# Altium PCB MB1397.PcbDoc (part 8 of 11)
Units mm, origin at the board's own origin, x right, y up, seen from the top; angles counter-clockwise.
Board outline 118.24 x 172.86 mm, 6 copper layers (Top Layer, L2_GND, L3_VCC, L4_SIG, L5_GND, Bottom Layer), stack 1.631 mm thick; 819 components, 632 nets, 2875 pads, 1523 vias.
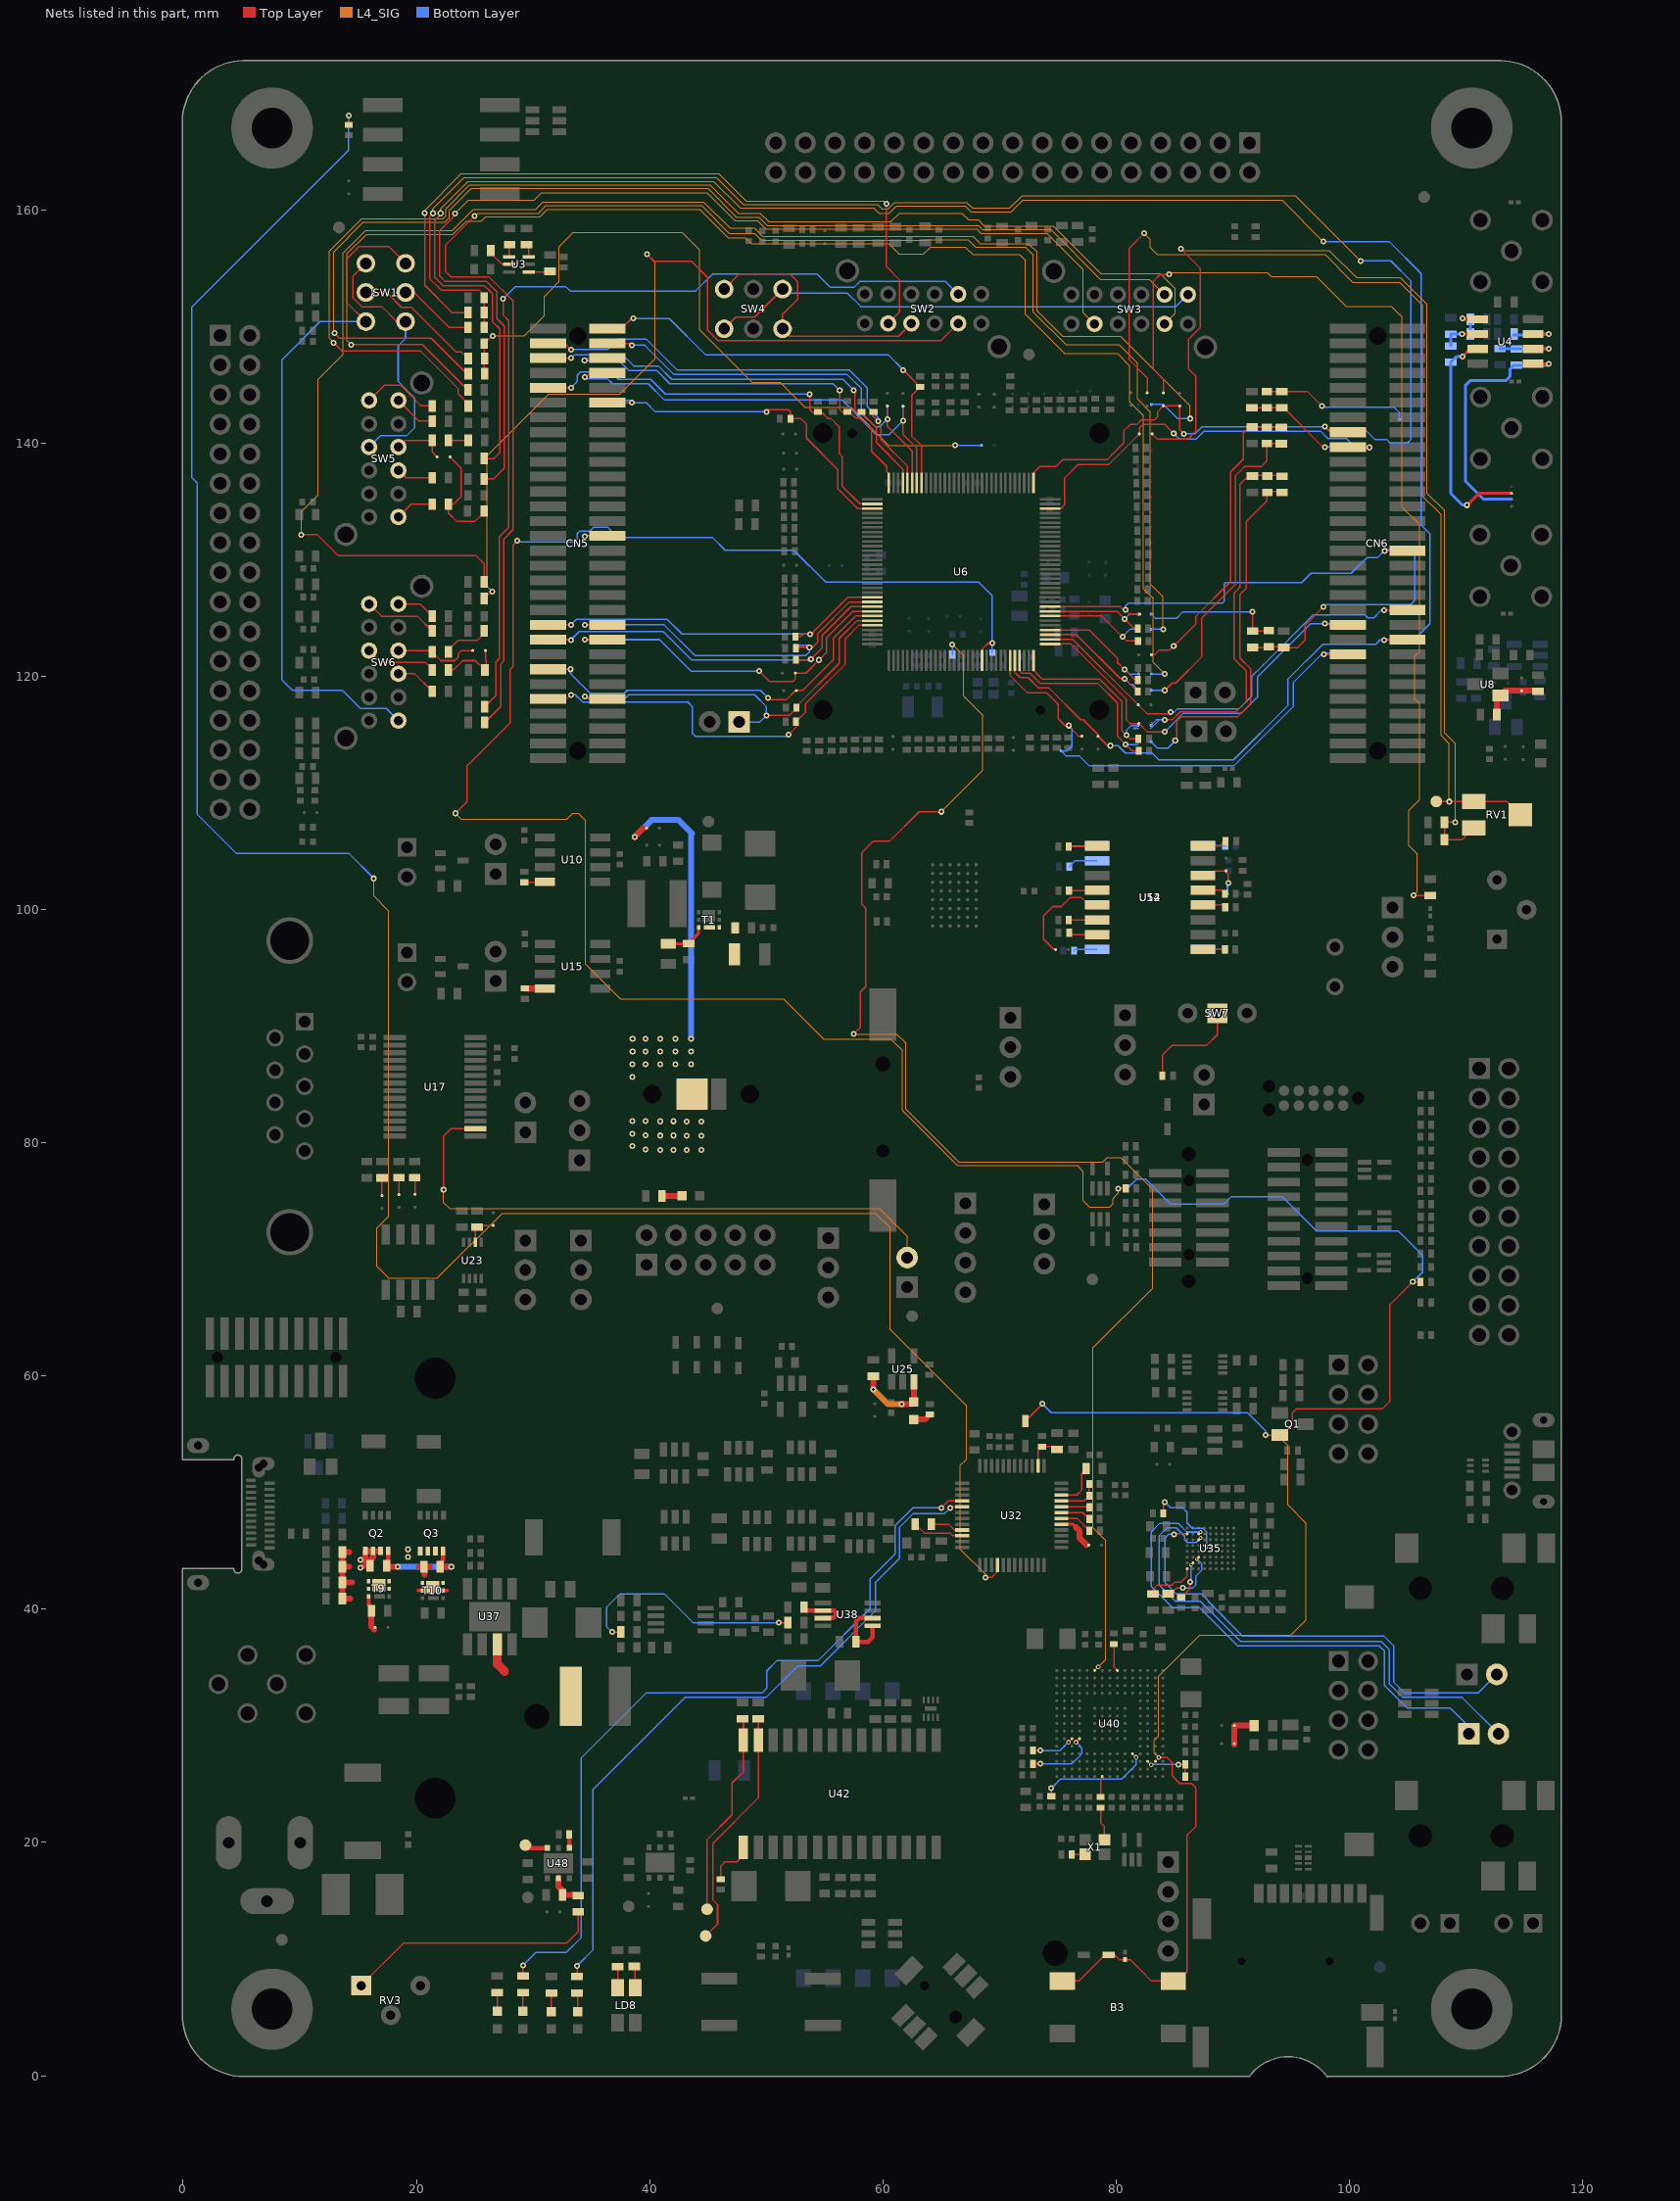
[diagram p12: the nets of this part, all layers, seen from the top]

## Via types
v1: diameter 0.508, hole 0.254, Top Layer to Bottom Layer, tented both sides, 1330 vias
v2: diameter 0.406, hole 0.203, Top Layer to Bottom Layer, tented both sides, 115 vias
v3: diameter 0.508, hole 0.254, Top Layer to Bottom Layer, 33 vias
v4: diameter 0.305, hole 0.152, Top Layer to Bottom Layer, tented both sides, 26 vias
v5: diameter 0.61, hole 0.305, Top Layer to Bottom Layer, tented both sides, 14 vias
v6: diameter 0.61, hole 0.33, Top Layer to Bottom Layer, tented both sides, 2 vias
v7: diameter 0.381, hole 0.203, Top Layer to Bottom Layer, tented both sides, 2 vias
v8: diameter 0.508, hole 0.203, Top Layer to Bottom Layer, tented both sides, 1 vias

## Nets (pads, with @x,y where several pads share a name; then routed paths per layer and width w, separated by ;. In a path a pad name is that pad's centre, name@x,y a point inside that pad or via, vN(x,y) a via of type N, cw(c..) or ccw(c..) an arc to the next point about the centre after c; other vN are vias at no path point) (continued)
NetJP16_2: JP16.2 U35.B1 | length 40.8
  Top Layer w0.127: v1(84.96,46.429) 84.996,46.464 U35.B1@86.077,46.466
  Bottom Layer w0.127: v1(84.96,46.429) 84.503,46.429 84.173,46.098 84.173,42.288 85.164,41.298 87.323,41.298 87.912,40.709 87.912,40.632 90.825,37.719 102.921,37.719 103.81,36.83 103.81,33.737 104.733,32.814 111.021,32.814 JP16.2@112.624,34.417
NetJP17_1: JP17.1 U35.B3 | length 44.3
  Top Layer w0.127: U35.B3@87.077,46.466 v4(87.236,46.624)
  Bottom Layer w0.127: v4(87.236,46.624) 86.06,46.624 85.316,47.368 83.741,47.368 83.005,46.632 83.005,41.958 84.808,40.155 87.119,40.155 90.399,36.876 102.539,36.876 102.987,36.428 102.987,33.482 104.948,31.521 108.644,31.521 110.236,29.929 JP17.1@110.236,29.314
NetJP17_2: JP17.2 U35.C3 | length 45.3
  Top Layer w0.127: U35.C3@87.077,45.966 v4(87.236,46.124)
  Bottom Layer w0.127: v4(87.236,46.124) 86.83,45.717 86.089,45.717 85.862,45.944 85.862,45.988 85.852,45.998 85.852,46.274 85.138,46.987 84.376,46.987 83.665,46.276 83.665,42.111 85.087,40.688 87.221,40.688 90.653,37.257 102.697,37.257 103.429,36.525 103.429,33.58 104.575,32.433 109.654,32.433 JP17.2@112.776,29.314
NetJP18_2: JP18.2 U17.16 | length 51.4
  Top Layer w0.127: v1(22.324,75.994) 22.324,80.566 22.971,81.213 U17.16@25.04,81.213
  L4_SIG w0.102: v1(22.324,75.994) 22.324,74.882 22.863,74.343 59.693,74.343 62.078,71.958 JP18.2@62.078,70.155
NetL5_1: L5.1 U37.7 | length 2.6
  Top Layer w0.762: U37.7@26.924,36.995 U37.7@26.924,36.986 26.924,35.306 27.559,34.671
NetL6_1: L6.1 SB45.2 SB46.2 | length 3.3
  Top Layer w0.508: SB46.2@90.134,28.402 SB45.2@90.135,30.023 L6.1@91.834,30.023
NetLD1_2: LD1.2 R297.1 | length 1.6
  Top Layer w0.127: LD1.2@26.924,5.516 R297.1@26.924,7.143
NetLD2_2: LD2.2 R298.1 | length 1.6
  Top Layer w0.127: R298.1@29.136,7.143 29.141,7.135 29.141,5.514 LD2.2@29.143,5.516
NetLD3_2: LD3.2 R299.1 | length 1.6
  Top Layer w0.127: LD3.2@31.567,5.502 31.565,5.502 31.565,7.099 R299.1@31.567,7.1
NetLD4_2: LD4.2 R300.1 | length 1.6
  Top Layer w0.127: R300.1@33.782,7.1 33.81,7.071 LD4.2@33.81,5.502
NetLD5_2: LD5.2 SB33.2 | length 25.1
  Top Layer w0.254: 39.464,106.977 SB33.2@39.742,106.977
  Top Layer w0.508: v1(38.707,106.22) 39.464,106.977 ; LD5.2@43.536,84.228 LD5.2@43.614,84.149
  Bottom Layer w0.508: v1(38.707,106.22) 40.155,107.668 42.466,107.668 43.614,106.52 43.536,106.441 v3(43.536,88.9)
  other v1: 44.434,79.364
  other v3: 43.179,79.385 39.634,79.408 40.889,79.387 42.048,79.39 38.529,79.731 44.436,80.594 40.892,80.617 42.051,80.62 43.181,80.614 39.637,80.637 38.506,80.769 44.436,81.813 40.892,81.836 42.051,81.839 43.181,81.834 38.506,81.862 39.637,81.856 38.504,85.636 40.915,86.716 42.215,86.716 43.533,86.716 38.529,86.741 39.66,86.736 40.917,87.808 42.217,87.808 43.536,87.808 38.532,87.833 39.662,87.828 40.917,88.9 42.217,88.9 38.532,88.925 39.662,88.92
NetLD6_1: LD6.1 R198.2 | length 1.7
  Top Layer w0.508: R198.2@41.062,75.442 LD6.1@42.784,75.442
NetLD7_1: LD7.1 R221.2 | length 1.6
  Top Layer w0.508: LD7.1@62.634,56.265 63.592,56.265 R221.2@64.028,56.7
NetLD7_2: LD7.2 R215.2 U25.3 | length 7
  Top Layer w0.508: v1(59.167,58.849) R215.2@59.167,59.978 ; v1(61.592,57.579) 62.438,57.579 LD7.2@62.637,57.778 62.649,57.79 U25.3@62.649,59.482
  L4_SIG w0.508: v1(59.167,58.849) 60.437,57.579 v1(61.592,57.579) v1@61.694,57.579
NetLD8_2: LD8.2 R296.1 | length 1.8
  Top Layer w0.127: R296.1@37.244,9.361 37.254,9.347 LD8.2@37.256,7.55
NetLD8_3: LD8.3 R295.1 | length 1.9
  Top Layer w0.127: R295.1@38.685,9.377 38.755,9.304 LD8.3@38.756,7.55
NetQ2_1: Q2.1 Q2.2 Q2.3 Q3.1 Q3.2 Q3.3 R248.2 | length 5
  Top Layer w0.508: v1(15.212,44.244) 15.528,44.244 15.627,44.146 ; 15.54,43.736 R248.2@16.036,43.736 ; Q2.3@16.886,45.005 Q2.2@16.277,45.005 ; 15.627,44.146 R248.2@16.036,43.736 ; 15.627,44.146 Q2.1@15.627,45.005 Q2.2@16.277,45.005 ; R248.2@16.036,43.736 R248.2@16.038,43.738 ; R248.2@16.036,43.736 16.038,43.736 R248.2@16.038,43.738 ; R248.2@16.038,43.738 16.038,44.195 16.277,44.434 Q2.2@16.277,45.005
  other v1: 15.216,43.561 19.276,44.498 19.276,45.133
NetQ2_4: Q2.4 Q3.4 R248.1 R249.2 | length 9.3
  Top Layer w0.381: R248.1@17.437,43.736 17.437,44.056 17.584,44.204 Q2.4@17.584,45.006 ; R249.2@22.088,43.645 22.088,44.008 22.283,44.204 Q3.4@22.283,45.004
  Top Layer w0.508: R248.1@17.437,43.736 17.529,43.645 v1(18.412,43.645) ; R249.2@22.088,43.645 v1(22.995,43.645)
  Bottom Layer w0.508: v1(18.412,43.645) v1(22.995,43.645)
NetR1_2: R1.2 U32.28 | length 200.9
  Top Layer w0.127: R1.2@14.191,167.277 v1(14.191,168.069) ; v1(68.806,42.72) 69.314,42.72 69.807,43.213 U32.28@69.807,43.79
  L4_SIG w0.102: v1(16.355,102.664) 16.355,101.14 17.625,99.87 17.625,73.708 16.609,72.692 16.609,69.39 17.6,68.4 21.791,68.4 27.353,73.962 59.357,73.962 60.604,72.715 60.604,64.003 67.155,57.452 67.155,52.88 66.647,52.372 66.647,45.133 68.806,42.974 v1(68.806,42.72)
  Bottom Layer w0.127: v1(14.191,168.069) 14.191,165.118 0.734,151.661 0.734,137.03 1.217,136.548 1.217,108.151 4.544,104.823 14.196,104.823 v1(16.355,102.664)
NetR13_2: R13.2 U3.6 | length 1.1
  Top Layer w0.127: R13.2@29.439,157.009 29.632,156.815 U3.6@29.632,155.971
NetR14_1: R14.1 U3.4 | length 1.8
  Top Layer w0.127: U3.4@29.632,154.671 31.394,154.671 R14.1@31.445,154.723
NetR15_2: R15.2 U3.2 | length 2.2
  Top Layer w0.127: R15.2@26.379,156.507 26.379,156.282 27.341,155.321 U3.2@27.932,155.321
NetR17_2: R17.2 U3.1 | length 1.1
  Top Layer w0.127: U3.1@27.932,155.971 27.932,156.95 R17.2@27.991,157.009
NetR20_2: R20.2 SW2.2 | length 64.2
  Top Layer w0.127: v1(20.724,159.7) 20.724,153.515 23.061,151.178 R20.2@24.417,151.178 ; v1(60.297,160.525) 60.297,155.115 61.44,153.972 61.44,151.254 SW2.2@60.446,150.262 SW2.2@60.446,150.262
  L4_SIG w0.102: v1(20.724,159.7) 20.724,159.967 23.848,163.091 45.926,163.091 48.263,160.754 60.068,160.754 v1(60.297,160.525)
NetR22_1: R22.1 SW1.5 | length 6.6
  Top Layer w0.127: SW1.5@19.068,152.908 19.807,152.908 22.807,149.908 R22.1@24.42,149.908
NetR24_1: R24.1 SW1.2 | length 11.1
  Top Layer w0.127: SW1.2@15.667,152.908 17.445,152.908 18.717,151.635 19.581,151.635 23.416,147.8 23.861,147.8 R24.1@24.42,147.241
NetR25_2: R25.2 SW3.8 | length 97.6
  Top Layer w0.127: v1(12.977,149.426) 13.409,148.994 21.267,148.994 R25.2@24.417,145.844
  L4_SIG w0.102: v1(12.977,149.426) 12.901,149.502 12.901,156.385 15.441,158.925 22.451,158.925 22.832,159.306 22.832,159.941 24.712,161.821 44.981,161.821 47.445,159.357 49.375,159.357 50.086,158.646 68.171,158.646 68.527,158.29 74.394,158.29 78.654,154.031 82.834,154.031 SW3.8@84.146,152.722
NetR51_2: R51.2 SW3.5 | length 105
  Top Layer w0.127: v1(12.913,148.6) 13.637,147.876 20.368,147.876 23.594,144.65 23.594,144.193 24.445,143.342 R51.2@24.446,143.184
  L4_SIG w0.102: v1(12.913,148.6) 12.545,148.968 12.545,156.461 15.314,159.23 22.273,159.23 22.527,159.484 22.527,160.094 24.559,162.126 45.184,162.126 47.597,159.713 49.451,159.713 50.188,158.976 60.678,158.976 61.415,159.713 66.749,159.713 67.333,159.128 68.171,159.128 68.704,158.595 74.597,158.595 78.661,154.531 83.741,154.531 85.062,153.21 85.062,151.138 SW3.5@84.146,150.222
NetR52_1: R52.1 SW5.9 | length 6.7
  Top Layer w0.127: SW5.9@15.95,143.65 SW5.9@15.951,143.647 ; SW5.9@15.95,143.65 17.257,144.955 18.641,144.955 20.419,143.177 R52.1@21.351,143.179
NetR55_1: R55.1 SW5.6 | length 3.6
  Top Layer w0.127: SW5.6@18.451,143.647 SW5.6@18.45,143.65 20.223,141.874 R55.1@21.351,141.875
NetR58_1: R58.1 SB14.1 SW5.4 | length 4.7
  Top Layer w0.127: SW5.4@18.45,139.65 19.03,140.228 R58.1@21.351,140.228 21.351,139.235 SB14.1@21.776,138.812
NetR58_2: R58.2 R59.1 | length 1.7
  Top Layer w0.127: R58.2@22.751,140.228 R59.1@24.446,140.228
NetR64_1: R64.1 SW5.3 | length 3.2
  Top Layer w0.127: SW5.3@18.45,137.65 19.083,137.015 R64.1@21.351,137.017
NetR66_2: R66.2 SW3.2 | length 91.2
  Top Layer w0.127: v1(23.315,159.687) 23.315,159.535 21.994,158.214 21.994,154.333 22.482,153.845 26.012,153.845 26.909,152.949 26.909,150.658 27.531,150.035 27.531,137.843 26.612,136.925 R66.2@25.813,136.925
  L4_SIG w0.102: v1(23.315,159.687) 24.458,160.83 30.096,160.83 30.706,161.44 44.905,161.44 47.292,159.052 49.248,159.052 49.959,158.341 68.044,158.341 68.4,157.985 74.064,157.985 77.188,154.861 77.188,151.178 SW3.2@78.146,150.222
NetR72_1: R72.1 SW5.1 | length 2.6
  Top Layer w0.127: 18.969,134.168 19.548,134.747 R72.1@21.342,134.747
NetR72_2: R72.2 R76.1 SB14.2 | length 9.6
  Top Layer w0.127: SB14.2@22.876,138.812 23.823,137.864 23.823,135.379 23.19,134.747 R72.2@22.742,134.747 22.742,133.996 23.467,133.271 24.996,133.271 R76.1@25.822,134.097
NetR95_2: R95.2 SW2.5 | length 72.9
  Top Layer w0.127: R95.2@25.821,126.67 26.403,127.251 v1(26.513,127.251) ; v1(39.774,156.182) 40.383,155.572 43.584,155.572 44.961,154.196 44.961,149.685 45.88,148.765 64.95,148.765 SW2.5@66.446,150.262
  L4_SIG w0.102: v1(26.513,127.251) 26.058,127.706 26.058,138.91 31.341,144.193 37.437,144.193 40.485,147.241 40.485,155.471 v1(39.774,156.182)
NetR99_1: R99.1 SW6.6 | length 3.3
  Top Layer w0.127: SW6.6@18.451,126.202 20.315,126.2 R99.1@21.351,125.166
NetR103_1: R103.1 SW6.9 | length 6.4
  Top Layer w0.127: SW6.9@15.951,126.202 17.008,125.143 20.086,125.143 R103.1@21.351,123.879
NetR104_1: R104.1 R110.2 | length 4
  Top Layer w0.127: R110.2@22.751,122.082 22.751,122.268 23.546,123.063 25.197,123.063 25.817,123.683 R104.1@25.817,123.873
NetR110_1: R110.1 SB19.1 SW6.4 | length 7.3
  Top Layer w0.127: SW6.4@18.451,122.202 21.229,122.202 22.098,121.333 23.289,121.333 23.569,121.613 23.569,121.917 23.847,122.196 SB19.1@24.824,122.196
NetR114_1: R114.1 SW6.7 | length 6.1
  Top Layer w0.127: SW6.7@15.951,122.202 16.944,121.206 20.737,121.206 R114.1@21.372,120.571
NetR114_2: R114.2 R115.1 SB19.2 | length 5.4
  Top Layer w0.127: R114.2@22.771,120.571 23.213,120.571 23.975,121.333 25.057,121.333 25.819,120.571 25.974,120.726 25.974,121.387 25.924,121.437 SB19.2@25.924,122.196
NetR117_1: R117.1 R124.2 SB22.2 U8.1 | length 5.2
  Top Layer w0.508: R124.2@112.633,116.698 112.631,118.024 U8.1@112.959,118.351 113.365,118.755 116.126,118.755 116.175,118.707 R117.1@116.176,118.707
NetR119_1: R119.1 SW6.3 | length 3.5
  Top Layer w0.127: SW6.3@18.451,120.202 19.855,120.2 R119.1@21.351,118.707
NetR122_2: R122.2 SW2.8 | length 77.4
  Top Layer w0.127: R122.2@25.846,117.373 26.822,118.35 26.822,121.234 27.102,121.514 27.102,131.953 27.912,132.763 27.912,150.495 27.432,150.975 v1(27.432,152.349)
  Bottom Layer w0.127: v1(27.432,152.349) 28.499,153.416 32.812,153.416 33.195,153.032 43.939,153.032 45.413,154.506 54.328,154.506 55.496,153.337 57.503,153.337 58.011,153.845 65.362,153.845 SW2.8@66.446,152.762
NetR159_2: R159.2 U12.8 | length 2.1
  Top Layer w0.127: U12.8@87.454,105.459 88.979,105.458 R159.2@89.38,105.861 R159.2@89.38,105.862
NetR160_1: R160.1 U12.9 | length 2.4
  Top Layer w0.127: R160.1@75.947,105.408 78.303,105.407 U12.9@78.354,105.459
NetR163_1: R163.1 U10.8 | length 1.8
  Top Layer w0.127: R163.1@29.25,102.332 30.983,102.332 U10.8@31.011,102.361
NetR167_1: R167.1 U12.12 | length 2.4
  Top Layer w0.127: R167.1@75.952,101.626 78.329,101.625 78.351,101.648 U12.12@78.354,101.649
NetR168_2: R168.2 U12.5 | length 2
  Top Layer w0.127: U12.5@87.454,101.649 89.035,101.648 R168.2@89.335,101.349
NetR169_2: R169.2 U12.4 | length 2
  Top Layer w0.127: U12.4@87.454,100.379 89.139,100.378 R169.2@89.344,100.175
NetR170_1: R170.1 U12.14 | length 2.4
  Top Layer w0.127: R170.1@75.947,99.086 78.329,99.085 78.351,99.108 U12.14@78.354,99.109
NetR172_1: R172.1 R177.2 T1.4 T1.7
NetR173_1: R173.1 U12.15 | length 2.4
  Top Layer w0.127: R173.1@75.987,97.965 76.054,97.899 76.116,97.838 U12.15@78.354,97.839
NetR175_2: R175.2 R176.2 T1.3 | length 3.4
  Top Layer w0.254: R175.2@41.6,97.072 43.302,97.071 44.199,97.968 T1.3@44.199,98.445
NetR178_2: R178.2 U12.1 | length 1.9
  Top Layer w0.127: U12.1@87.454,96.569 R178.2@89.312,96.569
NetR180_1: R180.1 U15.8 | length 1.7
  Top Layer w0.508: R180.1@29.309,93.208 29.319,93.218 U15.8@31.011,93.219
NetR182_2: R182.2 SW7.1 | length 9
  Top Layer w0.127: R182.2@83.96,85.75 83.96,87.507 84.816,88.363 87.762,88.363 88.666,89.268 SW7.1@88.666,91.107
NetR190_1: R190.1 SB39.2 | length 1.5
  Top Layer w0.127: R190.1@18.501,77.009 18.499,75.557 SB39.2@18.501,75.557
NetR191_2: R191.2 SB37.2 | length 1.4
  Top Layer w0.127: R191.2@19.847,77.009 19.881,76.975 SB37.2@19.88,75.577
NetR192_2: R192.2 SB38.1 | length 1.5
  Top Layer w0.127: SB38.1@17.044,75.462 R192.2@17.044,76.987
NetR202_1: R202.1 SB40.2 U23.2 | length 2.8
  Top Layer w0.127: U23.2@25.051,71.472 25.049,72.614 25.347,72.911 SB40.2@26.579,72.912
NetR223_1: R223.1 R224.2 U32.2 | length 3.2
  Top Layer w0.127: U32.2@73.307,52.292 73.307,53.607 R224.2@73.644,53.944 74.694,53.942 74.927,53.708 R223.1@74.929,53.709
NetR232_2: R232.2 U32.46 | length 3.9
  Top Layer w0.127: U32.46@75.307,49.792 76.614,49.792 77.061,50.239 77.061,51.694 R232.2@77.429,52.063
NetR234_1: R234.1 R235.2 U32.45 | length 3.6
  Top Layer w0.127: U32.45@75.307,49.292 77.254,49.291 R235.2@77.688,49.726 ; R234.1@77.679,50.741 77.678,50.742 77.688,50.731 R235.2@77.688,49.726 ; R235.2@77.688,49.725 R235.2@77.688,49.726
NetR236_1: R236.1 U32.44 | length 2.4
  Top Layer w0.127: U32.44@75.307,48.792 77.625,48.791 R236.1@77.679,48.738
NetR237_2: R237.2 U35.D4 U35.D5 | length 8.1
  Top Layer w0.127: R237.2@84.047,48.225 84.046,49.07 v1(84.173,49.197) ; U35.D4@87.577,45.466 v4(87.737,45.306) U35.D5@88.077,45.466
  Bottom Layer w0.127: v1(84.173,49.197) 84.681,48.689 85.722,48.689 86.078,48.334 86.078,47.394 86.535,46.937 87.424,46.937 87.737,46.624 v4(87.737,45.306)
NetR239_2: R239.2 U32.43 | length 2.6
  Top Layer w0.127: U32.43@75.307,48.292 77.125,48.29 R239.2@77.679,47.738
NetR240_1: R240.1 U32.21 | length 2.8
  Top Layer w0.127: R240.1@64.173,47.292 65.631,47.292 66.131,46.792 U32.21@66.807,46.792
NetR240_2: R240.2 U32.22 | length 4.4
  Top Layer w0.127: R240.2@62.774,47.292 63.536,46.53 65.758,46.53 65.997,46.292 U32.22@66.807,46.292
NetR243_2: R243.2 U32.42 | length 2.8
  Top Layer w0.127: U32.42@75.307,47.792 76.65,47.79 R243.2@77.704,46.738
NetR246_1: R246.1 R250.1 R254.1 R259.1 T9.1 T9.2 T9.5 T9.6 T9.8 | length 7.5
  Top Layer w0.508: 13.652,42.954 R250.1@13.654,43.634 ; R246.1@13.654,44.904 R246.1@13.652,45.029 ; 14.226,43.634 R250.1@13.654,43.634 ; 14.226,44.904 R246.1@13.654,44.904 R250.1@13.654,43.634 ; 14.329,40.906 R259.1@13.654,40.906 R254.1@13.654,42.306 ; 14.484,42.306 R254.1@13.654,42.306 ; R254.1@13.654,42.306 R250.1@13.654,43.634
NetR249_1: R249.1 T10.1 T10.2 T10.5 T10.6 T10.8 | length 2.5
  Top Layer w0.305: 20.13,41.613 T10.2@20.533,41.613 ; T10.5@22.283,41.613 22.669,41.613
  Top Layer w0.508: 20.19,43.645 R249.1@20.636,43.645 R249.1@20.688,43.645 ; 20.688,42.967 R249.1@20.688,43.645 ; 21.186,43.645 R249.1@20.688,43.645
NetR257_1: R257.1 U35.F3 | length 5.5
  Top Layer w0.127: R257.1@84.468,41.336 84.468,41.333 84.694,41.333 84.709,41.349 85.189,41.831 v1(85.697,41.831) ; v4(86.916,44.305) U35.F3@87.077,44.466
  Bottom Layer w0.127: v1(85.697,41.831) 86.586,41.831 86.84,42.085 86.84,42.847 87.348,43.355 87.348,43.873 v4(86.916,44.305)
NetR258_1: R258.1 U35.H1 | length 4.4
  Top Layer w0.127: R258.1@83.142,41.336 83.142,41.689 83.538,42.085 84.808,42.085 85.062,42.339 85.57,42.339 86.078,42.847 86.078,43.464 U35.H1@86.077,43.466
NetR261_2: R261.2 U35.G2 | length 3.4
  Top Layer w0.127: R261.2@85.57,41.015 86.332,41.775 v1(86.332,42.339) ; v4(86.416,43.805) U35.G2@86.577,43.966
  Bottom Layer w0.127: v1(86.332,42.339) 86.416,42.423 v4(86.416,43.805)
NetR262_1: R262.1 U38.6 U38.7 | length 4.4
  Top Layer w0.381: R262.1@53.239,40.179 53.528,39.891 55.816,39.891 55.979,39.726 55.979,39.51 55.71,39.24 U38.7@54.848,39.24
NetR263_2: R263.2 SB44.2 T9.3 | length 3
  Top Layer w0.305: T9.3@15.918,41.09 15.918,40.371 16.116,40.175 16.118,39.858 16.118,39.85 16.127,39.842 R263.2@16.144,39.825
  Top Layer w0.508: R263.2@16.144,39.825 16.144,38.524 16.391,38.275
NetR267_1: R267.1 R268.2 | length 20.1
  Top Layer w0.127: v1(36.774,38.05) R268.2@37.519,38.051 ; v1(51.087,38.849) R267.1@51.839,38.851
  Bottom Layer w0.127: v1(36.774,38.05) 36.294,38.53 36.294,40.162 37.455,41.323 41.247,41.323 43.721,38.849 v1(51.087,38.849)
NetR269_2: R269.2 U40.J15 | length 2.4
  Top Layer w0.127: R269.2@79.796,37.022 79.797,35.06 U40.J15@80.105,34.753
NetR270_1: R270.1 U38.1 U38.2 | length 5.9
  Top Layer w0.381: R270.1@57.677,37.208 R270.1@57.676,37.208 ; U38.1@59.098,38.59 59.098,37.589 58.717,37.208 R270.1@57.676,37.208 ; U38.2@59.098,39.24 57.96,39.24 57.676,38.956 R270.1@57.676,37.208
NetR273_1: R273.1 TP10.1 U42.28 | length 17.7
  Top Layer w0.127: TP10.1@44.93,14.272 44.93,20.241 47.066,22.377 47.066,25.095 48.043,26.072 U42.28@48.043,28.765 ; R273.1@47.974,30.612 48.044,30.541 U42.28@48.044,28.763
NetR274_1: R274.1 TP11.1 U42.27 | length 20.8
  Top Layer w0.127: TP11.1@44.803,11.986 45.819,13.002 45.819,14.672 45.438,15.053 45.438,19.934 49.313,23.809 U42.27@49.313,28.765 R274.1@49.313,30.612
NetR278_2: R278.2 U40.C6 | length 3.8
  Top Layer w0.127: R278.2@72.851,27.888 v1(73.505,27.887) ; v2(75.902,28.599) U40.C6@76.205,28.901
  Bottom Layer w0.127: v1(73.505,27.887) 75.189,27.887 v2@75.9,28.598
NetR280_2: R280.2 U40.D6 | length 6.2
  Top Layer w0.127: R280.2@72.851,26.751 v1(73.475,26.749) ; v2(76.552,28.599) U40.D6@76.855,28.901
  Bottom Layer w0.127: v1(73.475,26.749) 76.203,26.749 77.061,27.607 77.061,28.087 v2(76.552,28.599)
NetR281_1: R281.1 R282.1 U40.N3 | length 4.4
  Top Layer w0.127: U40.N3@82.705,26.953 v2(83.008,26.65) ; v1(85.347,26.688) R281.1@85.921,26.69 R282.1@85.921,25.656
  Bottom Layer w0.127: v2@83.007,26.647 83.009,26.649 83.05,26.688 v1(85.347,26.688)
NetR283_2: R283.2 U40.L4 | length 9.9
  Top Layer w0.127: R283.2@74.433,23.968 v1(74.432,24.648) ; U40.L4@81.405,27.603 v2(81.708,27.3)
  Bottom Layer w0.127: v1(74.432,24.648) 75.232,25.448 80.49,25.448 81.709,26.667 v2@81.709,27.297
NetR284_1: R284.1 X1.3 | length 2.9
  Top Layer w0.127: R284.1@78.664,22.999 78.664,21.687 78.989,21.361 X1.3@78.988,20.231
NetR284_2: R284.2 U40.G1 | length 1.8
  Top Layer w0.127: R284.2@78.664,23.899 78.664,25.509 U40.G1@78.805,25.653
NetR286_1: R286.1 U48.1 | length 1.2
  Top Layer w0.381: R286.1@33.105,20.688 33.117,20.676 U48.1@33.116,19.524
NetR288_2: R288.2 X1.1 | length 1.2
  Top Layer w0.127: R288.2@76.192,18.961 76.21,18.979 X1.1@77.338,18.981
NetR291_1: R291.1 U42.1 | length 4.1
  Top Layer w0.127: R291.1@46.103,16.852 46.104,17.986 46.454,18.336 47.47,18.336 48.044,18.91 48.044,19.583 U42.1@48.043,19.585
NetR292_1: R292.1 R293.2 U48.5 | length 2.9
  Top Layer w0.508: U48.5@32.166,16.924 32.167,16.241 32.515,15.893 32.515,15.499 33.818,15.499 R293.2@33.868,15.45
NetR293_1: R293.1 RV3.1 | length 22.2
  Top Layer w0.127: RV3.1@15.258,7.734 18.877,11.351 32.865,11.351 33.868,12.355 R293.1@33.868,14.05
NetR298_2: R298.2 U32.16 | length 67.9
  Top Layer w0.127: R298.2@29.136,8.543 v1(29.136,9.474) ; v1(64.996,48.689) 65.598,49.291 U32.16@66.807,49.292
  Bottom Layer w0.127: v1(29.136,9.474) 30.251,10.589 32.865,10.589 34.135,11.859 34.135,27.257 39.693,32.814 49.622,32.814 50.038,33.23 50.038,34.722 50.902,35.585 54.432,35.585 58.9,40.053 58.9,42.593 61.059,44.752 61.059,47.194 62.555,48.689 v1(64.996,48.689)
NetR300_2: R300.2 U32.17 | length 61.3
  Top Layer w0.127: R300.2@33.782,8.5 v1(33.782,9.431) ; v1(65.758,48.689) 65.86,48.791 U32.17@66.807,48.792
  Bottom Layer w0.127: v1(33.782,9.431) 35.151,10.8 35.151,24.559 43.025,32.433 49.987,32.433 52.682,35.128 54.61,35.128 59.345,39.863 59.345,42.276 61.44,44.371 61.44,47.036 62.586,48.181 65.25,48.181 v1(65.758,48.689)
NetR301_1: R301.1 R305.2 U4.5 | length 3.3
  Top Layer w0.254: v1(109.698,150.67) 109.761,150.607 U4.5@110.985,150.607
  Bottom Layer w0.254: v1(109.698,150.67) 109.761,150.607 R301.1@110.362,150.607 R305.2@110.362,149.337
NetR302_2: R302.2 R304.2 U4.3 | length 4.3
  Top Layer w0.254: U4.3@115.735,149.337 115.735,149.334 v1(117.066,149.334)
  Bottom Layer w0.254: R304.2@114.082,149.273 115.481,149.273 115.542,149.334 v1(117.066,149.334)
NetR303_1: R303.1 R306.2 U4.6 | length 3.3
  Top Layer w0.254: v1(109.67,149.337) U4.6@110.985,149.337
  Bottom Layer w0.254: R306.2@108.684,148.323 R303.1@108.684,149.332 108.684,149.337 v1(109.67,149.337)
NetR306_1: R306.1 SB16.1 U4.7 | length 20.1
  Top Layer w0.254: v1(109.7,147.419) 110.348,148.067 U4.7@110.985,148.067 ; v1(110.081,134.668) 111.097,135.684 113.881,135.684 SB16.1@113.891,135.677
  Bottom Layer w0.254: v1(109.7,147.419) 109.179,147.419 108.684,146.924 108.684,135.684 109.7,134.668 v1(110.081,134.668)
NetR307_1: R307.1 R308.2 U4.2 | length 5.5
  Top Layer w0.254: U4.2@115.735,148.067 v1(117.066,148.067)
  Bottom Layer w0.254: R307.1@112.903,148.103 114.28,148.102 R308.2@114.311,148.073 114.318,148.067 v1(117.066,148.067)
NetR308_1: R308.1 SB75.1 U4.1 | length 22.4
  Top Layer w0.254: U4.1@115.735,146.797 v1(117.066,146.797)
  Bottom Layer w0.254: SB75.1@113.891,135.184 111.47,135.184 109.954,136.7 109.954,144.955 110.335,145.336 113.393,145.336 113.764,145.707 113.764,146.352 114.084,146.672 116.942,146.672 v1(117.066,146.797)
NetR312_1: R312.1 U40.F15 | length 121.1
  Top Layer w0.127: v1(57.503,89.329) 58.056,89.882 58.056,92.93 58.519,93.393 58.519,100.124 58.189,100.454 58.189,104.874 59.154,105.839 60.551,105.839 63.091,108.379 v1(64.996,108.379) ; U40.F15@78.155,34.753 v2(78.457,35.055)
  L4_SIG w0.102: v1(57.503,89.329) 61.186,89.329 61.948,88.567 61.948,88.059 61.973,88.034 61.973,82.89 66.507,78.356 78.834,78.356 79.22,78.743 80.409,78.743 83.132,76.02 83.132,67.528 78.026,62.423 78.026,46.962 79.093,45.895 79.093,35.69 v2@78.476,35.075 ; v1(64.996,108.379) 68.552,111.935 68.552,116.634 66.901,118.285 66.901,121.78 v1(65.951,122.73)
  Bottom Layer w0.127: R312.1@65.953,121.866 v1(65.951,122.73)
NetR319_2: R319.2 U54.1 | length 1.9
  Bottom Layer w0.127: U54.1@87.454,105.459 87.478,105.484 R319.2@89.347,105.485
NetR320_1: R320.1 U54.15 | length 2.6
  Bottom Layer w0.127: R320.1@75.988,103.681 76.495,104.188 U54.15@78.354,104.189
NetR321_2: R321.2 U54.8 | length 1.9
  Bottom Layer w0.127: U54.8@87.454,96.569 87.452,96.571 89.311,96.571 R321.2@89.312,96.569
NetR322_1: R322.1 U54.9 | length 2
  Bottom Layer w0.127: R322.1@76.379,96.468 76.479,96.568 U54.9@78.354,96.569
NetSB35_2: SB35.2 SB120.2 U12.6 | length 4.2
  Top Layer w0.127: U12.6@87.454,102.919 88.082,102.918 88.476,103.309 SB35.2@89.418,103.312 89.418,103.21 89.601,103.027 v1(89.601,102.265)
  Bottom Layer w0.127: SB120.2@89.535,101.349 89.535,102.197 v1(89.601,102.265)
NetSB36_1: SB36.1 U12.13 | length 8.9
  Top Layer w0.127: SB36.1@74.801,96.572 74.646,96.571 73.759,97.457 73.759,99.444 74.567,100.251 75.283,100.251 76.045,101.013 77.01,101.013 77.645,100.378 U12.13@78.354,100.379
NetSB43_1: SB43.1 U32.41 | length 3.3
  Top Layer w0.254: U32.41@75.307,47.292 75.306,47.292 76.299,47.292 76.553,47.036
  Top Layer w0.508: 76.553,47.036 76.871,46.718 76.871,46.086 77.455,45.502
NetSB119_1: SB119.1 U54.16 | length 2.4
  Bottom Layer w0.127: SB119.1@75.997,105.408 76.048,105.458 U54.16@78.354,105.459
NetSW1_1: SW1.1 SW1.6 SW5.7 | length 23.3
  Top Layer w0.127: SW1.1@15.667,155.407 14.552,154.292 14.552,152.448 15.314,151.686 17.041,151.686 18.321,150.406 SW1.6@19.068,150.406
  Bottom Layer w0.127: SW5.7@15.951,139.649 SW5.7@15.95,139.65 SW5.7@15.95,139.65 16.914,140.612 19.149,140.612 19.86,141.323 19.86,143.838 18.438,145.26 18.438,148.333 19.068,148.963 SW1.6@19.068,150.406
NetSW1_3: SW1.3 SW1.4 SW6.1 | length 59.6
  Top Layer w0.127: SW1.3@15.667,150.407 13.993,152.08 13.993,155.75 15.085,156.842 17.63,156.842 18.548,155.926 SW1.4@19.067,155.408
  Bottom Layer w0.127: SW1.3@15.667,150.407 11.747,150.406 8.481,147.14 8.481,119.682 9.37,118.793 13.663,118.793 15.212,117.244 17.407,117.244 SW6.1@18.451,116.202
NetSW2_3: SW2.3 SW4.3 SW4.4 | length 23.5
  Top Layer w0.127: SW4.4@46.389,153.192 47.678,154.48 52.042,154.48 52.677,153.845 52.677,152.321 51.425,151.069 51.389,151.069 SW4.3@51.389,149.792 52.032,149.146 61.331,149.146 SW2.3@62.446,150.262
NetSW3_9: SW3.9 SW4.1 SW4.6 | length 42.2
  Top Layer w0.127: SW4.1@46.389,149.792 47.394,150.797 48.994,150.797 SW4.6@51.389,153.192
  Bottom Layer w0.127: SW4.6@51.389,153.192 51.725,152.855 56.944,152.855 58.113,151.686 85.11,151.686 SW3.9@86.146,152.722
NetTP7_1: TP7.1 U48.3 | length 2
  Top Layer w0.381: TP7.1@29.35,19.774 29.599,19.522 U48.3@31.216,19.524
NRST: B3.3 B3.4 C174.2 D7.2 D11.1 Q1.2 R196.2 R211.2 R309.2 U6.21 U40.P3 U51.1 | length 314.7
  Top Layer w0.127: v1(23.34,108.252) 24.356,109.268 24.356,112.316 28.039,115.999 28.039,120.571 28.27,120.802 28.27,131.229 v1(28.661,131.62) ; U6.21@68.503,121.346 68.504,121.346 68.504,122.301 69.06,122.857 v1(69.375,122.857) ; D7.2@72.207,56.137 v1(73.678,57.61) ; B3.4@75.39,8.125 76.795,8.125 79.033,10.363 D11.1@79.353,10.363 79.857,10.363 80.263,9.957 U51.1@80.767,9.957 ; v1(80.188,76.076) R196.2@80.823,76.077 ; U51.1@80.767,9.962 81.203,9.962 82.054,9.109 83.038,8.124 83.489,8.124 83.49,8.123 85.323,8.123 86.078,8.878 86.078,20.622 86.84,21.384 86.84,24.686 86.459,25.067 85.443,25.067 84.808,25.702 84.808,26.845 84.356,27.297 v2@83.658,27.297 ; U40.P3@83.355,26.953 83.658,27.256 v2(83.658,27.287) v2@83.658,27.297 ; v2@83.658,27.3 v2@83.658,27.297 ; v1(92.809,54.928) Q1.2@94.023,54.928 ; Q1.2@94.023,54.93 Q1.2@94.023,54.928 ; R211.2@106.091,68.072 v1(105.43,68.072) 103.477,66.116 103.477,57.833 102.842,57.198 95.476,57.198 95.095,56.817 95.095,55.801 94.221,54.928 Q1.2@94.023,54.928
  L4_SIG w0.102: v1(23.34,108.252) 23.848,107.744 32.916,107.744 33.424,108.252 33.881,108.252 34.516,107.617 34.516,95.298 37.462,92.352 51.458,92.352 54.912,88.897 60.678,88.897 61.669,87.907 61.669,82.764 66.381,78.052 76.655,78.052 77.188,77.518 77.188,75.027 77.719,74.496 79.449,74.496 79.715,74.762 79.715,75.22 80.188,75.692 v1(80.188,76.076) ; v2@83.657,27.297 83.259,27.696 83.259,28.776 83.614,29.131 83.614,34.262 87.145,37.793 94.993,37.793 96.289,39.088 96.289,47.368 94.714,48.943 94.714,54.023 93.81,54.928 v1(92.809,54.928)
  Bottom Layer w0.127: v1(28.661,131.62) 28.674,131.62 28.776,131.519 33.551,131.519 33.779,131.747 33.779,132.23 34.008,132.458 34.872,132.458 35.176,132.763 36.421,132.763 36.645,132.54 R309.2@36.645,132.08 36.85,131.874 45.408,131.874 46.472,130.81 52.344,130.81 55.09,128.064 68.199,128.064 69.372,126.891 69.372,122.86 v1(69.375,122.857) C174.2@69.375,122.022 ; v1(73.678,57.61) 74.445,56.843 91.26,56.843 92.809,55.293 v1(92.809,54.928) ; v1(80.188,76.076) 80.952,76.076 81.76,76.883 82.522,76.883 84.681,74.724 89.202,74.724 89.837,75.359 94.257,75.359 97.178,72.438 104.188,72.438 106.271,70.355 106.271,68.91 v1(105.43,68.072)
NRST_E: CN5.30 R309.1 | length 3.3
  Top Layer w0.127: v1(34.44,132.001) 34.465,132.029 CN5.30@36.385,132.031
  Bottom Layer w0.127: v1(34.44,132.001) 34.514,132.077 35.029,132.077 35.032,132.08 R309.1@35.745,132.08
OPAMP1_INN: C20.1 R65.2 R67.2 SB105.1 | length 33.2
  Top Layer w0.127: v1(84.173,116.253) 84.781,116.253 85.479,116.952 90.251,116.952 91.138,117.839 91.138,120.467 90.094,121.511 90.094,127.127 90.625,127.658 90.625,136.472 91.376,137.224 92.936,137.224 92.939,137.226 R67.2@94.176,137.226
  Bottom Layer w0.127: SB105.1@82.974,115.789 83.438,116.253 83.69,116.253 ; 82.974,115.537 82.974,115.54 83.099,115.663 83.69,116.253 ; v1(84.173,116.253) 83.69,116.253
OPAMP1_INP: R61.2 SB95.1 | length 149.2
  Top Layer w0.127: v1(22.07,159.695) 22.07,159.568 21.562,159.06 21.562,154.226 22.324,153.464 25.855,153.464 26.262,153.057 ; R61.2@25.813,138.674 26.634,138.674 27.15,139.19 27.15,149.781 26.53,150.401 26.53,152.792 26.264,153.058
  L4_SIG w0.102: v1(22.07,159.695) 22.07,160.094 24.407,162.43 45.466,162.43 47.752,160.144 59.205,160.144 59.662,159.687 60.526,159.687 61.161,160.322 67.028,160.322 67.536,159.814 70.99,159.814 72.006,160.83 94.206,160.83 v1(97.762,157.274)
  Bottom Layer w0.127: v1(97.762,157.274) 103.396,157.274 106.144,154.526 106.144,132.966 106.906,132.204 106.906,124.508 105.509,123.111 SB95.1@105.375,123.111
OPAMP1_OUT: C20.2 R67.1 SB117.1 | length 32
  Top Layer w0.127: v1(85.062,114.475) 85.189,114.602 85.189,116.126 85.602,116.539 90.428,116.539 91.516,117.627 91.516,120.654 90.602,121.568 90.602,127 91.158,127.556 91.158,133.271 92.936,135.049 92.936,135.824 94.173,135.824 R67.1@94.176,135.827
  Bottom Layer w0.127: SB117.1@82.989,114.387 83.537,113.84 84.427,113.84 v1(85.062,114.475)
OPAMP2_IN1P: R31.2 SB101.1 | length 125.8
  Top Layer w0.127: v1(14.425,148.435) 20.526,148.435 R31.2@24.421,144.542
  L4_SIG w0.102: v1(14.425,148.435) 14.069,148.791 14.069,156.233 15.72,157.884 23.137,157.884 24.28,159.027 25.55,159.027 25.918,159.395 30.592,159.395 31.239,160.043 44.27,160.043 46.708,157.604 48.207,157.604 48.74,157.071 60.5,157.071 61.364,156.207 63.497,156.207 64.107,156.817 67.056,156.817 67.716,156.157 71.727,156.157 72.21,155.674 72.21,151.051 75.588,147.673 80.109,147.673 81.176,146.606 81.176,143.507 82.319,142.364 82.319,127.505 83.157,126.667 83.157,121.204 v1(84.173,120.19)
  Bottom Layer w0.127: SB101.1@83.022,120.19 v1(84.173,120.19)
OPAMP2_IN2P: C15.1 R24.2 R25.1 SB70.1 | length 63.6
  Top Layer w0.127: R25.1@25.817,145.844 25.819,145.847 25.819,147.241 25.817,147.244 25.817,148.511 26.497,149.192 v1(26.54,149.192)
  L4_SIG w0.102: v1(26.54,149.192) 29.253,149.192 30.96,150.899 30.96,152.575 32.23,153.845 32.23,156.833 33.47,158.073 42.76,158.073 44.295,156.538 44.295,149.68 48.765,145.209 51.153,145.209 53.312,143.05 57.249,143.05 60.498,139.802 v1(66.192,139.802)
  Bottom Layer w0.127: v1(66.192,139.802) SB70.1@68.441,139.802
OPAMP2_INN: C19.1 R56.2 R57.2 SB20.1 | length 26.4
  Top Layer w0.127: SB20.1@83.025,121.844 83.287,121.844 83.665,122.222 84.554,122.222 v1(84.935,122.603) 86.84,124.508 86.84,125.143 89.812,128.115 89.812,137.513 90.904,138.605 90.904,140.84 91.396,141.332 R56.2@91.641,141.332 ; R56.2@91.645,141.356 92.905,141.356 92.908,141.36 94.146,141.36 R57.2@94.168,141.337
OPAMP2_OUT: C19.2 R57.1 SB104.1 | length 28.2
  Top Layer w0.127: v1(84.173,118.793) 84.808,119.428 85.105,119.428 87.348,121.671 87.348,125.016 90.244,127.912 90.244,137.208 91.006,137.97 92.428,137.97 92.916,138.458 92.916,139.906 92.947,139.937 R57.1@94.168,139.937
  Bottom Layer w0.127: SB104.1@83.022,118.793 v1(84.173,118.793)
OPAMP3_INN: C27.1 R105.2 R106.2 SB80.1 | length 20.8
  Top Layer w0.127: R105.2@91.702,122.467 93.033,122.466 C27.1@93.086,122.521 94.295,122.519 R106.2@94.349,122.467 95.567,122.466 96.187,123.086 96.187,124.356 v1(97.775,125.943)
  Bottom Layer w0.127: v1(97.775,125.943) 97.991,126.159 105.255,126.159 105.598,126.502 105.598,130.632 105.437,130.795 105.374,130.858
OPAMP3_INP: R125.2 SB94.1 | length 140.2
  Top Layer w0.127: v1(24.991,159.459) 22.476,156.944 22.476,154.734 22.987,154.224 26.257,154.224 28.293,152.188 28.293,132.565 27.483,131.755 27.483,121.285 27.229,121.031 27.229,117.412 R125.2@25.847,116.027
  L4_SIG w0.102: v1(24.991,159.459) 25.245,159.713 30.452,159.713 31.087,160.348 44.447,160.348 46.81,157.985 48.969,157.985 49.578,157.376 63.805,157.376 63.856,157.427 67.31,157.427 67.945,156.792 72.21,156.792 72.895,156.106 72.895,151.229 75.689,148.435 80.236,148.435 81.811,146.86 81.811,143.761 82.928,142.644 82.928,127.912 84.021,126.82 v1(84.021,124.028)
  Bottom Layer w0.127: SB94.1@83.007,124.028 v1(84.021,124.028)
OPAMP3_OUT: C27.2 R105.1 SB91.1 | length 12.1
  Top Layer w0.127: v1(91.666,125.524) 91.702,125.489 R105.1@91.702,123.867 93.033,123.866 C27.2@93.086,123.921
  Bottom Layer w0.127: SB91.1@82.998,125.324 83.368,124.953 85.143,124.953 85.717,125.524 v1(91.666,125.524)
OPAMP4/COMP6_INP: R164.1 SB8.2 | length 86
  Top Layer w0.127: SB8.2@84.046,144.285 84.046,145.463 83.157,146.352 83.157,153.845 83.767,154.455 v1(84.554,154.455) ; v1(105.477,101.2) R164.1@106.934,101.2
  L4_SIG w0.102: v1(84.554,154.455) 84.706,154.607 92.961,154.607 93.292,154.277 97.173,154.277 99.713,151.737 103.579,151.737 104.518,150.797 104.518,134.516 106.017,133.017 106.017,122.121 105.611,121.714 105.611,118.057 106.017,117.65 106.017,109.446 105.077,108.506 105.077,105.484 105.814,104.747 105.814,101.537 v1(105.477,101.2)
OPAMP4_IN1P: C14.1 R20.1 R22.2 SB67.1 | length 123.1
  Top Layer w0.127: v1(21.41,159.695) 21.13,159.415 21.13,154.099 22.146,153.083 25.397,153.083 C14.1@25.817,152.664 ; C14.1@25.813,152.448 25.813,151.188 R20.1@25.821,151.181 R22.2@25.821,149.911
  L4_SIG w0.102: v1(21.41,159.695) 21.41,160.068 24.102,162.761 45.697,162.761 48.009,160.449 59.535,160.449 59.916,160.068 60.449,160.068 61.008,160.627 67.18,160.627 67.663,160.144 70.879,160.144 71.945,161.211 95.349,161.211 v1(100.942,155.618)
  Bottom Layer w0.127: SB67.1@100.292,141.145 100.294,141.148 101.341,141.148 102.182,140.307 103.172,140.307 103.477,140.002 104.976,140.002 105.28,140.307 105.28,153.871 103.533,155.618 v1(100.942,155.618)
OPAMP4_IN2P: R91.2 SB63.1 | length 133.4
  Top Layer w0.127: v1(10.132,132.128) 11.502,132.128 13.305,130.325 25.118,130.325 25.821,129.622 R91.2@25.821,128.079
  L4_SIG w0.102: v1(10.132,132.128) 10.132,134.107 11.557,135.532 11.557,145.44 13.713,147.597 13.713,156.309 15.644,158.239 23.061,158.239 24.864,160.043 30.223,160.043 30.858,160.678 44.625,160.678 46.886,158.417 48.969,158.417 49.654,157.731 67.714,157.731 68.349,157.096 72.464,157.096 73.2,156.36 73.2,151.354 75.408,149.146 80.363,149.146 86.332,143.177 v1(86.332,142.098)
  Bottom Layer w0.127: SB63.1@83.022,143.304 83.022,143.307 84.046,143.307 85.25,142.098 v1(86.332,142.098)
OpAmp4_INM: R157.1 R158.1 RV1.1 SB11.2 | length 95
  Top Layer w0.127: SB11.2@83.114,140.787 SB11.2@83.078,140.788 83.53,140.335 ; 83.566,140.335 86.157,140.335 86.84,141.018 86.84,145.717 86.205,146.352 86.205,148.892 87.221,149.908 87.221,154.963 v1(85.545,156.639) ; v1(109.065,107.49) 109.052,107.478 R157.1@108.142,107.479 R158.1@108.142,105.983 109.654,105.982 RV1.1@110.649,106.979
  L4_SIG w0.102: v1(85.545,156.639) 85.697,156.487 98.27,156.487 100.581,154.175 104.341,154.175 106.652,151.864 106.652,135.684 108.151,134.186 108.151,115.136 109.065,114.221 v1(109.065,107.49)
OPAMP4_INN: C17.1 R32.2 R33.2 SB71.1 | length 9.1
  Top Layer w0.127: R32.2@91.645,143.024 91.646,143.025 91.658,143.012 92.913,143.012 92.926,143.025 R33.2@94.186,143.025 ; R33.2@94.185,143.024 R33.2@94.186,143.025 ; v1(97.889,139.652) 97.732,139.652 94.358,143.025 R33.2@94.186,143.025
  Bottom Layer w0.127: v1(97.889,139.652) SB71.1@99.365,139.652
OPAMP4_OUT: C17.2 R33.1 SB65.1 | length 12.7
  Top Layer w0.127: C17.2@92.913,144.412 92.926,144.424 96.388,144.424 v1(97.635,143.177)
  Bottom Layer w0.127: v1(97.635,143.177) 97.762,143.05 103.833,143.05 104.264,142.618 SB65.1@104.264,141.976
OpAmp4_VOUT: RV1.2 RV1.3 SB7.2 TP2.1 | length 92.9
  Top Layer w0.127: v1(82.395,157.985) 81.125,156.715 81.125,147.114 82.649,145.59 SB7.2@82.649,144.285 ; TP2.1@107.442,109.258 v1(108.557,109.258) 110.627,109.258 RV1.3@110.649,109.279 113.497,109.278 RV1.2@114.649,108.129
  L4_SIG w0.102: v1(82.395,157.985) 82.941,157.439 82.941,156.754 83.513,156.182 97.894,156.182 100.282,153.794 104.29,153.794 106.271,151.813 106.271,135.43 107.846,133.855 107.846,114.932 108.557,114.221 v1(108.557,109.258)
PA0: CN6.45 SB26.2 SB98.2 SB116.1 U6.27 | length 45.2
  Top Layer w0.127: U6.27@70.903,121.346 70.902,120.068 72.367,118.603 74.011,118.603 74.826,117.785 75.029,117.582 75.029,116.355 75.613,115.771 v1(75.918,115.771) 75.918,115.697 76.759,114.859 SB26.2@77.064,114.859 ; v1(97.79,121.869) CN6.45@99.865,121.871
  Bottom Layer w0.127: v1(75.918,115.771) 76.197,115.491 76.197,114.003 75.791,113.596 75.283,113.596 75.722,113.154 76.858,113.154 77.704,112.309 90.084,112.309 95.199,117.424 95.199,119.482 97.587,121.869 v1(97.79,121.869) 97.892,121.971 SB98.2@99.321,121.971 SB98.2@99.322,121.968
PA1: CN6.44 SB27.2 SB95.2 U6.28 | length 44.8
  Top Layer w0.127: U6.28@71.303,121.346 71.303,120.333 71.417,120.218 71.417,120.216 71.75,119.883 72.456,119.883 73.355,118.984 74.242,118.984 76.949,116.276 77.165,116.276 78.435,115.006 SB27.2@78.435,114.854 78.463,114.854 79.276,114.038 79.284,114.046 v1(79.502,114.046) ; v1(102.969,123.111) 102.997,123.139 CN6.44@104.965,123.141
  Bottom Layer w0.127: v1(79.502,114.046) 80.157,114.046 80.78,113.424 83.066,113.424 83.665,112.824 90.064,112.824 94.712,117.472 94.712,119.74 97.702,122.73 102.232,122.73 102.613,123.111 v1(102.969,123.111) SB95.2@104.275,123.111
PA2: R150.2 SB117.2 U6.29 | length 16.7
  Top Layer w0.127: U6.29@71.703,121.346 71.702,120.475 71.798,120.378 71.798,120.376 71.91,120.264 72.616,120.264 73.515,119.365 78.445,119.365 80.109,117.699 80.109,114.856 v1(80.808,114.158) 81.365,113.6 R150.2@81.922,113.6
  Bottom Layer w0.127: v1(80.808,114.158) 80.828,114.137 81.89,114.137
PA3: R129.2 SB105.2 U6.32 | length 16.2
  Top Layer w0.127: U6.32@72.903,121.346 72.903,120.518 73.675,119.746 78.603,119.746 80.49,117.859 80.49,115.319 v1(80.874,114.935) 81.186,114.623 R129.2@81.907,114.623
  Bottom Layer w0.127: v1(80.874,114.935) 80.874,115.364 81.298,115.789 SB105.2@81.874,115.789 ; 81.476,115.537 81.478,115.54 81.874,115.54 81.874,115.537 81.476,115.537
PA4: CN6.41 SB25.2 SB93.2 U6.33 | length 36.2
  Top Layer w0.127: U6.33@74.323,122.766 76.136,122.766 80.874,118.026 80.874,116.253 81.176,115.951 SB25.2@81.95,115.951 82.657,115.242 84.165,115.242 v1(84.173,115.237) ; v1@97.889,124.508 97.988,124.409 v1@97.991,124.409 ; v1(97.889,124.511) v1@97.991,124.409 ; CN6.41@99.865,124.411 v1@97.991,124.409
  Bottom Layer w0.127: v1(84.173,115.237) 85.766,116.83 90.731,116.83 92.126,118.224 92.126,119.951 92.489,120.314 92.489,120.317 96.683,124.511 v1(97.889,124.511) 99.322,124.511 SB93.2@99.319,124.508
PA5: CN6.40 SB24.2 U6.34 | length 38.2
  Top Layer w0.127: U6.34@74.323,123.166 76.276,123.165 SB24.2@81.89,117.551 82.68,116.761 84.511,116.761 v1(84.666,116.916) ; v1(102.984,125.667) 102.997,125.679 CN6.40@104.965,125.681
  Bottom Layer w0.127: v1(84.666,116.916) 84.958,116.916 85.25,117.208 90.534,117.208 91.618,118.292 91.618,119.981 92.634,120.997 92.634,121.001 96.904,125.27 101.318,125.27 101.572,125.016 102.08,125.016 102.73,125.667 v1(102.984,125.667)
PA6: R121.2 SB104.2 U6.35 | length 11.1
  Top Layer w0.127: U6.35@74.323,123.566 74.323,123.563 76.228,123.563 76.246,123.546 76.609,123.546 80.363,119.791 v1(80.726,119.791) R121.2@81.834,118.684
  Bottom Layer w0.127: v1(80.726,119.791) 81.214,119.301 81.415,119.301 SB104.2@81.922,118.793
PA7: R118.2 SB101.2 U6.36 | length 10.9
  Top Layer w0.127: U6.36@74.323,123.966 77.701,123.965 80.109,121.554 80.109,121.186 v1(80.726,120.571) 81.631,119.667 R118.2@81.846,119.667
  Bottom Layer w0.127: v1(80.726,120.571) 81.107,120.19 SB101.2@81.922,120.19
PA8: CN5.2 R30.2 U6.89 | length 38.5
  Top Layer w0.127: CN5.2@36.385,149.811 37.592,149.809 38.453,150.67 v1(38.58,150.67) ; v1(61.752,146.251) R30.2@63.19,144.813 ; R30.2@63.19,144.81 R30.2@63.19,144.813 ; U6.89@63.303,136.586 63.302,139.758 62.459,140.602 62.459,144.082 R30.2@63.19,144.813
  Bottom Layer w0.127: v1(38.58,150.67) 41.676,150.67 44.775,147.571 60.429,147.571 v1(61.752,146.251)
PA9: CN5.8 SB4.2 SB54.2 U6.90 | length 40.2
  Top Layer w0.127: v1(34.44,145.641) 34.541,145.641 34.902,146.002 36.386,146.002 CN5.8@36.385,146.001 ; SB4.2@61.721,143.151 61.722,143.152 v1(61.722,141.907) 61.722,140.739 62.903,139.558 U6.90@62.903,136.586
  Bottom Layer w0.127: v1(34.44,145.641) 34.567,145.517 36.373,145.517 36.807,145.082 39.875,145.082 41.245,143.713 56.457,143.713 57.76,142.41 57.76,142.385 59.432,140.713 60.528,140.713 v1(61.722,141.907) 61.722,143.152 SB54.2@61.721,143.151
PA10: CN5.4 SB3.2 SB53.2 U6.91 | length 37.1
  Top Layer w0.127: CN5.4@36.385,148.541 38.298,148.539 v1(38.453,148.384) ; SB3.2@60.366,143.154 60.376,143.165 v1(60.376,142.034) 60.376,141.458 62.502,139.332 U6.91@62.503,136.586
  Bottom Layer w0.127: v1(38.453,148.384) 39.571,148.384 42.085,145.87 56.944,145.87 58.138,144.676 58.138,142.565 59.304,141.399 59.741,141.399 v1(60.376,142.034) SB53.2@60.376,143.18
PA11: CN5.3 R46.2 U6.92 | length 40.6
  Top Layer w0.127: CN5.3@31.285,148.541 31.285,148.542 32.71,148.542 v1(33.246,148.003) ; R46.2@59.154,142.601 59.154,142.314 v1(59.586,141.882) 59.586,141.703 59.831,141.459 59.831,140.266 ; 60.159,139.938 59.831,140.266 ; U6.92@62.103,136.586 62.103,137.995 59.833,140.266 59.831,140.266
  Bottom Layer w0.127: v1(33.246,148.003) 36.421,148.003 37.31,148.892 39.721,148.892 42.337,146.276 57.097,146.276 58.646,144.727 58.646,143.126 59.586,142.187 v1(59.586,141.882)
PA12: CN5.5 R45.2 U6.93 | length 37.5
  Top Layer w0.127: CN5.5@31.285,147.271 31.285,147.272 v1(33.246,147.272) ; v1(57.495,144.531) 57.582,144.445 57.582,142.845 57.826,142.601 58.153,142.601 59.446,141.307 59.446,140.038 61.719,137.765 U6.93@61.719,136.586
  Bottom Layer w0.127: v1(33.246,147.272) 33.523,147.549 37.694,147.549 38.636,146.606 40.747,146.606 41.887,145.463 56.563,145.463 v1(57.495,144.531)
PA13: CN5.6 R44.2 U6.96 | length 35.6
  Top Layer w0.127: v1(34.417,147.066) 34.62,147.269 CN5.6@36.385,147.271 ; v1(56.297,144.511) 56.317,144.49 56.317,142.839 56.48,142.676 R44.2@56.946,142.676 ; 56.556,142.601 57.197,142.601 57.636,142.161 58.005,142.161 58.107,142.06 58.11,142.06 58.747,141.424 ; 58.745,141.425 58.747,141.424 ; U6.96@60.503,136.586 60.503,137.363 60.325,137.541 60.325,137.98 59.028,139.277 59.028,141.142 58.747,141.424
  Bottom Layer w0.127: v1(34.417,147.066) 37.363,147.066 38.204,146.225 40.587,146.225 41.73,145.082 55.725,145.082 v1(56.297,144.511)
PA14: CN5.9 R47.2 U6.98 | length 37
  Top Layer w0.127: CN5.9@31.285,144.731 31.285,144.732 v1(33.246,144.732) ; v1(53.718,144.193) 53.718,142.894 54.011,142.601 54.778,142.601 55.268,142.11 55.522,142.11 56.261,141.374 56.261,139.085 56.495,138.852 56.495,136.299 58.011,134.785 58.092,134.785 58.105,134.772 59.075,134.772 U6.98@59.083,134.766
  Bottom Layer w0.127: v1(33.246,144.732) 33.782,145.268 33.782,145.796 34.087,146.101 36.678,146.101 37.315,145.463 40.079,145.463 41.349,144.193 v1(53.718,144.193)
PA15: CN5.12 R54.2 SB62.2 U6.99 | length 30.2
  Top Layer w0.127: CN5.12@36.385,143.461 v1(38.481,143.459) ; v1(50.01,142.669) 50.216,142.875 51.879,142.875 52.06,142.694 R54.2@52.06,142.085 52.959,142.085 53.439,141.605 53.439,140.414 56.114,137.739 56.114,136.088 57.836,134.366 U6.99@59.083,134.366
  Bottom Layer w0.127: SB62.2@37.049,143.637 38.303,143.637 v1(38.481,143.459) 39.703,143.459 40.49,142.669 v1(50.01,142.669)
PB0: R108.1 SB94.2 U6.39 | length 10.6
  Top Layer w0.127: U6.39@74.323,125.166 78.743,125.166 80.891,123.017 ; v1(80.546,123.393) 80.891,123.017 ; R108.1@81.871,123.018 80.891,123.017
  Bottom Layer w0.127: v1(80.546,123.393) 81.181,124.028 SB94.2@81.907,124.028
PB1: R102.1 SB91.2 U6.40 | length 9.5
  Top Layer w0.127: U6.40@74.323,125.566 80.068,125.565 v1(80.729,124.907) 81.557,124.079 R102.1@81.844,124.079
  Bottom Layer w0.127: v1(80.729,124.907) 81.148,125.324 SB91.2@81.898,125.324
PB2: CN6.32 SB18.1 SB80.2 U6.41 | length 36.6
  Top Layer w0.127: U6.41@74.323,125.948 74.495,125.948 74.517,125.97 80.329,125.97 80.594,125.705 v1(80.797,125.705) 81.178,125.324 SB18.1@82.025,125.324 ; v1(102.997,130.759) CN6.32@104.965,130.761
  Bottom Layer w0.127: v1(80.797,125.705) 80.797,126.009 81.05,126.262 81.253,126.262 81.277,126.286 89.126,126.286 89.266,126.426 89.266,127.912 89.393,128.039 95.9,128.039 96.688,128.826 100.145,128.826 101.476,130.16 102.398,130.16 v1(102.997,130.759) 103.096,130.858 SB80.2@104.275,130.858
PB3: CN5.41 R107.1 U6.118 | length 31.3
  Top Layer w0.127: CN5.41@31.285,124.411 v1(33.246,124.409) ; R107.1@52.495,123.393 52.967,123.393 53.193,123.619 v1(53.739,123.619) 53.998,123.619 54.026,123.647 54.026,123.812 56.98,126.766 59.083,126.766 U6.118@59.083,126.766
  Bottom Layer w0.127: v1(33.246,124.409) 33.726,124.889 41.501,124.889 42.771,123.619 v1(53.739,123.619)
PB4: CN5.42 R109.2 SB96.1 U6.119 | length 32.7
  Top Layer w0.127: v1(34.44,124.409) CN5.42@36.385,124.411 ; R109.2@52.528,122.411 52.593,122.476 v1(53.693,122.476) 53.947,122.476 54.407,122.936 54.407,123.652 57.12,126.365 U6.119@59.083,126.366
  Bottom Layer w0.127: v1(34.44,124.409) 41.247,124.409 43.878,121.778 53.376,121.778 53.693,122.095 v1(53.693,122.476) 53.513,122.657 SB96.1@52.472,122.657
PB5: CN5.43 R112.1 U6.120 | length 32.9
  Top Layer w0.127: CN5.43@31.285,123.141 33.218,123.139 v1(33.246,123.111) ; R112.1@52.528,121.412 53.772,121.412 v1(53.82,121.46) 54.788,122.428 54.788,123.492 57.262,125.966 59.083,125.966 U6.120@59.083,125.966
  Bottom Layer w0.127: v1(33.246,123.111) 33.96,123.825 41.168,123.825 43.597,121.397 53.533,121.397 53.597,121.46 v1(53.82,121.46)
PB6: CN5.44 SB21.1 U6.121 | length 31.6
  Top Layer w0.127: v1(34.44,123.139) CN5.44@36.385,123.141 ; v1(49.375,120.444) 50.289,119.53 52.258,119.53 52.479,119.748 SB21.1@52.479,120.264 ; SB21.1@52.487,120.269 53.391,120.269 v1(54.519,121.397) 55.169,122.047 55.169,123.307 57.427,125.565 U6.121@59.083,125.566
  Bottom Layer w0.127: v1(34.44,123.139) 40.836,123.139 43.536,120.444 v1(49.375,120.444)
PB7: CN5.47 SB23.2 U6.122 | length 33.4
  Top Layer w0.127: CN5.47@31.285,120.601 v1(33.221,120.599) ; v1(50.137,118.158) 50.312,117.983 51.702,117.983 52.514,118.793 53.134,118.793 55.753,121.412 55.753,123.274 57.645,125.166 U6.122@59.083,125.166
  Bottom Layer w0.127: v1(33.221,120.599) 33.221,120.216 34.897,118.539 37.818,118.539 38.072,118.793 49.502,118.793 v1(50.137,118.158)
PB8: CN5.52 JP1.1 R123.2 U6.123 | length 35.6
  Top Layer w0.127: v1(34.44,118.285) 34.666,118.059 CN5.52@36.385,118.061 ; v1(50.01,116.634) 50.043,116.667 52.017,116.667 52.611,117.259 R123.2@52.621,117.269 ; R123.2@52.574,117.299 R123.2@52.621,117.297 ; R123.2@52.619,117.269 R123.2@52.621,117.269 ; U6.123@59.083,124.766 57.785,124.765 56.261,123.241 56.261,121.1 52.621,117.46 R123.2@52.621,117.297 ; R123.2@52.621,117.269 R123.2@52.621,117.297
  Bottom Layer w0.127: v1(34.44,118.285) 34.567,118.158 37.976,118.158 38.23,118.412 48.992,118.412 50.01,117.394 v1(50.01,116.634) 49.431,116.055 JP1.1@47.495,116.055
PB9: CN5.51 R127.1 U6.124 | length 36.7
  Top Layer w0.127: CN5.51@31.285,118.061 32.893,118.059 v1(33.246,118.412) ; v1(51.915,114.983) 52.545,115.613 R127.1@52.547,116.098 ; R127.1@52.547,116.098 53.365,116.916 53.365,117.64 53.784,118.059 53.784,118.073 53.876,118.164 53.89,118.164 56.769,121.044 56.769,123.208 57.925,124.363 U6.124@59.083,124.363
  Bottom Layer w0.127: v1(33.246,118.412) 33.627,118.412 34.262,117.777 43.279,117.777 43.66,117.396 43.66,115.11 43.914,114.856 51.788,114.856 v1(51.915,114.983)
PB10: CN6.17 SB11.1 SB71.2 U6.62 | length 34.6
  Top Layer w0.127: U6.62@74.981,134.366 75.235,134.366 75.59,134.722 75.59,137.008 76.733,138.15 79.338,138.15 79.365,138.176 SB11.1@81.978,140.788 81.978,141.262 82.118,141.402 82.166,141.453 82.319,141.605 84.145,141.605 v1(84.935,140.815) ; CN6.17@99.865,139.651 101.669,139.649 v1(101.699,139.621)
  Bottom Layer w0.127: v1(84.935,140.815) 85.402,140.345 86.863,140.345 87.536,141.018 97.508,141.018 98.143,140.383 99.736,140.383 SB71.2@100.465,139.652 ; SB71.2@100.429,139.621 v1(101.699,139.621)
PB11: CN6.15 SB8.1 SB10.1 SB67.2 U6.65 | length 35.1
  Top Layer w0.127: U6.65@72.903,136.586 72.903,137.447 73.426,137.97 74.823,137.97 75.408,138.554 79.199,138.554 79.863,139.215 80.64,139.995 80.64,141.028 81.191,141.58 81.755,141.58 82.159,141.983 83.309,141.983 83.411,142.085 83.411,142.11 83.538,142.237 83.538,142.677 84.046,143.185 SB10.1@85.443,143.185 ; SB10.1@85.443,143.172 85.443,141.145 v1(85.799,140.79) ; v1(97.889,141.399) 98.367,140.922 99.865,140.922 CN6.15@99.865,140.921
  Bottom Layer w0.127: v1(85.799,140.79) 86.769,140.79 87.379,141.399 v1(97.889,141.399) 98.143,141.145 SB67.2@99.192,141.145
